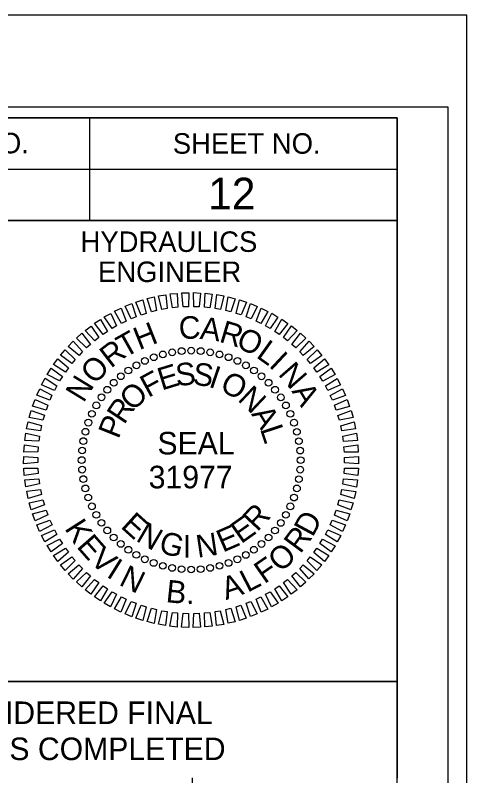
# Model space of a CAD drawing. Extents: x 557032 to 558840, y 515971 to 517218.
# Drawn here: x 558606.3 to 558716.5, y 517032.6 to 517218.2 of the extents above; entities that cross this region are included whole.
import ezdxf

# ---------------------------------------------------------------- set-up
doc = ezdxf.new("R2010")
doc.units = 0
for name, color, linetype in [('Default', 7, 'Continuous'), ('Sheet Cutting Line CELL', 7, 'Continuous'), ('Sheet Data Field CELL', 7, 'Continuous'), ('Sheet Plot Border Inside CELL', 7, 'Continuous'), ('Sheet Plot Border Outside CELL', 7, 'Continuous'), ('Sheet Profile CELL', 7, 'Continuous'), ('Sheet Profile Grid Major CELL', 7, 'Continuous'), ('Sheet Sticker Exception Certification CELL', 7, 'Continuous')]:
    doc.layers.add(name, color=color, linetype=linetype)

msp = doc.modelspace()

# ---------------------------------------------------------------- linework, layer by layer
at = {"layer": 'Default'}
for points in [[(558639.58, 517145.8), (558638.5, 517149.06), (558640.23, 517149.46), (558640.8, 517146.11)], [(558642.12, 517146.38), (558641.27, 517149.71), (558643.03, 517149.99), (558643.36, 517146.61)], [(558644.7, 517146.79), (558644.09, 517150.17), (558645.86, 517150.32), (558645.95, 517146.93)], [(558647.31, 517147.01), (558646.93, 517150.43), (558648.71, 517150.46), (558648.56, 517147.07)], [(558649.92, 517147.06), (558649.78, 517150.49), (558651.55, 517150.4), (558651.18, 517147.02)], [(558652.53, 517146.92), (558652.63, 517150.35), (558654.39, 517150.13), (558653.78, 517146.79)], [(558655.12, 517146.6), (558655.46, 517150.02), (558657.2, 517149.68), (558656.36, 517146.39)], [(558657.68, 517146.1), (558658.26, 517149.48), (558659.98, 517149.02), (558658.9, 517145.8)], [(558634.64, 517144.1), (558633.12, 517147.18), (558634.78, 517147.82), (558635.8, 517144.58)], [(558637.08, 517145.03), (558635.78, 517148.21), (558637.48, 517148.73), (558638.27, 517145.43)], [(558660.2, 517145.42), (558661.02, 517148.76), (558662.7, 517148.18), (558661.4, 517145.04)], [(558662.67, 517144.57), (558663.72, 517147.84), (558665.35, 517147.14), (558663.84, 517144.1)], [(558629.99, 517141.74), (558628.05, 517144.57), (558629.61, 517145.43), (558631.07, 517142.37)], [(558632.27, 517143), (558630.54, 517145.96), (558632.15, 517146.72), (558633.4, 517143.56)], [(558665.08, 517143.54), (558666.34, 517146.74), (558667.93, 517145.93), (558666.21, 517143)], [(558667.4, 517142.36), (558668.89, 517145.45), (558670.41, 517144.53), (558668.5, 517141.73)], [(558627.8, 517140.31), (558625.67, 517143.01), (558627.16, 517143.98), (558628.83, 517141.02)], [(558669.64, 517141.01), (558671.34, 517143.99), (558672.8, 517142.97), (558670.69, 517140.31)], [(558625.71, 517138.74), (558623.4, 517141.28), (558624.82, 517142.35), (558626.7, 517139.52)], [(558671.78, 517139.51), (558673.68, 517142.37), (558675.06, 517141.25), (558672.77, 517138.74)], [(558623.74, 517137.03), (558621.25, 517139.4), (558622.59, 517140.57), (558624.67, 517137.88)], [(558673.81, 517137.86), (558675.91, 517140.58), (558677.21, 517139.37), (558674.75, 517137.03)], [(558621.89, 517135.19), (558619.24, 517137.38), (558620.5, 517138.64), (558622.76, 517136.1)], [(558675.72, 517136.08), (558678, 517138.65), (558679.21, 517137.34), (558676.59, 517135.18)], [(558620.17, 517133.22), (558617.38, 517135.22), (558618.55, 517136.56), (558620.98, 517134.19)], [(558677.5, 517134.17), (558679.95, 517136.57), (558681.07, 517135.19), (558678.31, 517133.21)], [(558618.6, 517131.13), (558615.67, 517132.94), (558616.75, 517134.36), (558619.33, 517132.16)], [(558679.14, 517132.14), (558681.76, 517134.36), (558682.78, 517132.9), (558679.88, 517131.12)], [(558617.17, 517128.94), (558614.13, 517130.54), (558615.1, 517132.03), (558617.83, 517130.01)], [(558680.63, 517130), (558683.4, 517132.03), (558684.32, 517130.51), (558681.31, 517128.93)], [(558615.91, 517126.66), (558612.76, 517128.04), (558613.62, 517129.6), (558616.49, 517127.77)], [(558681.98, 517127.76), (558684.88, 517129.59), (558685.69, 517128.01), (558682.57, 517126.65)], [(558614.8, 517124.29), (558611.57, 517125.45), (558612.32, 517127.06), (558615.3, 517125.45)], [(558683.16, 517125.43), (558686.18, 517127.06), (558686.88, 517125.42), (558683.68, 517124.28)], [(558613.86, 517121.86), (558610.55, 517122.78), (558611.19, 517124.45), (558614.29, 517123.04)], [(558684.18, 517123.02), (558687.31, 517124.44), (558687.89, 517122.76), (558684.62, 517121.84)], [(558613.1, 517119.36), (558609.73, 517120.05), (558610.25, 517121.76), (558613.44, 517120.57)], [(558685.03, 517120.55), (558688.25, 517121.75), (558688.71, 517120.03), (558685.38, 517119.35)], [(558612.51, 517116.82), (558609.1, 517117.27), (558609.5, 517119.01), (558612.76, 517118.05)], [(558685.7, 517118.03), (558689, 517119), (558689.34, 517117.25), (558685.97, 517116.8)], [(558612.1, 517114.24), (558608.67, 517114.46), (558608.95, 517116.21), (558612.26, 517115.48)], [(558686.2, 517115.46), (558689.55, 517116.2), (558689.77, 517114.43), (558686.38, 517114.22)], [(558611.87, 517111.63), (558608.43, 517111.61), (558608.59, 517113.39), (558611.95, 517112.89)], [(558686.51, 517112.87), (558689.91, 517113.37), (558690, 517111.59), (558686.61, 517111.62)], [(558611.82, 517109.02), (558608.39, 517108.76), (558608.42, 517110.54), (558611.81, 517110.28)], [(558686.65, 517110.26), (558690.07, 517110.52), (558690.04, 517108.74), (558686.65, 517109.01)], [(558611.95, 517106.41), (558608.55, 517105.92), (558608.46, 517107.69), (558611.86, 517107.67)], [(558686.6, 517107.65), (558690.03, 517107.67), (558689.88, 517105.9), (558686.52, 517106.4)], [(558612.27, 517103.82), (558608.91, 517103.09), (558608.7, 517104.85), (558612.09, 517105.07)], [(558686.37, 517105.05), (558689.8, 517104.83), (558689.52, 517103.07), (558686.2, 517103.8)], [(558612.76, 517101.26), (558609.47, 517100.29), (558609.13, 517102.04), (558612.5, 517102.49)], [(558685.96, 517102.47), (558689.36, 517102.01), (558688.96, 517100.28), (558685.7, 517101.24)], [(558613.44, 517098.73), (558610.22, 517097.54), (558609.76, 517099.26), (558613.08, 517099.94)], [(558685.37, 517099.93), (558688.73, 517099.23), (558688.21, 517097.53), (558685.03, 517098.72)], [(558614.29, 517096.26), (558611.16, 517094.85), (558610.58, 517096.53), (558613.85, 517097.44)], [(558684.6, 517097.43), (558687.91, 517096.5), (558687.27, 517094.84), (558684.18, 517096.25)], [(558615.31, 517093.86), (558612.28, 517092.23), (558611.59, 517093.87), (558614.79, 517095)], [(558683.66, 517094.99), (558686.9, 517093.84), (558686.15, 517092.22), (558683.16, 517093.84)], [(558616.49, 517091.53), (558613.59, 517089.69), (558612.78, 517091.28), (558615.89, 517092.64)], [(558682.56, 517092.63), (558685.71, 517091.25), (558684.84, 517089.69), (558681.98, 517091.51)], [(558617.83, 517089.29), (558615.06, 517087.25), (558614.15, 517088.78), (558617.16, 517090.35)], [(558681.29, 517090.34), (558684.33, 517088.75), (558683.36, 517087.26), (558680.63, 517089.27)], [(558619.33, 517087.15), (558616.71, 517084.93), (558615.69, 517086.38), (558618.58, 517088.16)], [(558679.87, 517088.15), (558682.79, 517086.35), (558681.72, 517084.93), (558679.13, 517087.13)], [(558620.97, 517085.12), (558618.51, 517082.72), (558617.39, 517084.1), (558620.16, 517086.08)], [(558678.29, 517086.07), (558681.08, 517084.07), (558679.92, 517082.72), (558677.49, 517085.1)], [(558622.75, 517083.21), (558620.47, 517080.64), (558619.25, 517081.94), (558621.87, 517084.11)], [(558676.58, 517084.1), (558679.22, 517081.91), (558677.96, 517080.65), (558675.71, 517083.19)], [(558624.66, 517081.42), (558622.56, 517078.7), (558621.26, 517079.92), (558623.72, 517082.26)], [(558626.69, 517079.78), (558624.78, 517076.92), (558623.4, 517078.04), (558625.69, 517080.55)], [(558672.76, 517080.54), (558675.07, 517078), (558673.65, 517076.93), (558671.77, 517079.76)], [(558674.73, 517082.25), (558677.21, 517079.88), (558675.87, 517078.72), (558673.8, 517081.41)], [(558628.83, 517078.28), (558627.13, 517075.29), (558625.67, 517076.31), (558627.78, 517078.98)], [(558670.67, 517078.97), (558672.8, 517076.28), (558671.31, 517075.31), (558669.63, 517078.26)], [(558631.06, 517076.93), (558629.58, 517073.83), (558628.05, 517074.75), (558629.97, 517077.55)], [(558668.48, 517077.55), (558670.42, 517074.72), (558668.86, 517073.85), (558667.39, 517076.92)], [(558633.39, 517075.74), (558632.12, 517072.55), (558630.54, 517073.36), (558632.26, 517076.29)], [(558635.79, 517074.72), (558634.75, 517071.45), (558633.11, 517072.14), (558634.62, 517075.18)], [(558663.82, 517075.19), (558665.35, 517072.11), (558663.69, 517071.47), (558662.66, 517074.71)], [(558666.19, 517076.29), (558667.93, 517073.32), (558666.31, 517072.57), (558665.06, 517075.73)], [(558638.26, 517073.87), (558637.45, 517070.53), (558635.77, 517071.11), (558637.06, 517074.25)], [(558640.78, 517073.19), (558640.21, 517069.8), (558638.49, 517070.27), (558639.56, 517073.49)], [(558658.89, 517073.49), (558659.97, 517070.23), (558658.23, 517069.83), (558657.67, 517073.18)], [(558661.38, 517074.25), (558662.69, 517071.07), (558660.99, 517070.56), (558660.19, 517073.86)], [(558643.35, 517072.69), (558643.01, 517069.27), (558641.26, 517069.61), (558642.11, 517072.9)], [(558645.94, 517072.37), (558645.84, 517068.93), (558644.07, 517069.15), (558644.69, 517072.49)], [(558648.55, 517072.23), (558648.69, 517068.8), (558646.91, 517068.89), (558647.29, 517072.27)], [(558651.16, 517072.27), (558651.54, 517068.86), (558649.76, 517068.83), (558649.9, 517072.22)], [(558653.76, 517072.5), (558654.38, 517069.12), (558652.6, 517068.97), (558652.51, 517072.36)], [(558656.34, 517072.91), (558657.19, 517069.58), (558655.43, 517069.3), (558655.1, 517072.68)]]:
    msp.add_lwpolyline(points, close=True, dxfattribs=at)
for centre in [(558642.33, 517135.43), (558644.6, 517135.93), (558646.91, 517136.24), (558649.24, 517136.34), (558651.56, 517136.24), (558653.87, 517135.93), (558656.15, 517135.43), (558637.96, 517133.84), (558640.11, 517134.73), (558658.37, 517134.73), (558660.52, 517133.84), (558635.89, 517132.77), (558662.59, 517132.76), (558632.08, 517130.1), (558633.92, 517131.51), (558664.55, 517131.51), (558666.4, 517130.09), (558630.36, 517128.52), (558668.11, 517128.52), (558628.79, 517126.81), (558669.69, 517126.8), (558627.37, 517124.96), (558671.1, 517124.95), (558626.12, 517123), (558672.35, 517122.99), (558625.04, 517120.93), (558673.43, 517120.92), (558624.15, 517118.78), (558674.32, 517118.77), (558623.45, 517116.56), (558675.02, 517116.55), (558622.94, 517114.28), (558675.52, 517114.27), (558622.64, 517111.98), (558675.83, 517111.97), (558622.54, 517109.65), (558675.93, 517109.64), (558622.64, 517107.32), (558675.83, 517107.31), (558622.94, 517105.01), (558675.52, 517105), (558623.44, 517102.74), (558675.02, 517102.73), (558624.14, 517100.52), (558674.32, 517100.51), (558625.04, 517098.37), (558673.43, 517098.36), (558626.11, 517096.3), (558672.35, 517096.29), (558627.36, 517094.34), (558671.1, 517094.33), (558628.78, 517092.49), (558630.35, 517090.77), (558668.11, 517090.76), (558669.68, 517092.48), (558632.07, 517089.2), (558666.39, 517089.19), (558633.92, 517087.78), (558664.54, 517087.77), (558635.88, 517086.53), (558637.95, 517085.45), (558660.51, 517085.45), (558662.58, 517086.52), (558640.1, 517084.56), (558642.32, 517083.86), (558644.59, 517083.35), (558653.86, 517083.35), (558656.14, 517083.86), (558658.36, 517084.56), (558646.9, 517083.05), (558649.23, 517082.95), (558651.55, 517083.05)]:
    msp.add_circle(centre, 0.826, dxfattribs=at)
at = {"layer": 'Sheet Cutting Line CELL'}
msp.add_line((558716.45, 517218.17), (557032.45, 517218.17), dxfattribs=at)
at = {"layer": 'Sheet Plot Border Inside CELL'}
msp.add_lwpolyline([(557045.45, 516140.62), (558711.95, 516140.62), (558711.95, 517195.72), (557045.45, 517195.72)], close=True, dxfattribs=at)
at = {"layer": 'Sheet Plot Border Outside CELL'}
msp.add_lwpolyline([(557032.45, 516118.17), (558716.45, 516118.17), (558716.45, 517218.17), (557032.45, 517218.17)], close=True, dxfattribs=at)
at = {"layer": 'Sheet Profile CELL'}
for p, q in [((558624.45, 517193.12), (558624.45, 517168.12)), ((558499.4, 517180.62), (558699.45, 517180.62))]:
    msp.add_line(p, q, dxfattribs=at)
for points in [[(558699.45, 517193.17), (557199.45, 517193.17), (557199.45, 516143.17), (558699.45, 516143.17)], [(558499.4, 517193.17), (558699.45, 517193.17), (558699.45, 517168.12), (558499.4, 517168.12)], [(558599.45, 517168.12), (558699.45, 517168.12), (558699.45, 517055.62), (558599.45, 517055.62)]]:
    msp.add_lwpolyline(points, close=True, dxfattribs=at)
at = {"layer": 'Sheet Profile Grid Major CELL'}
msp.add_lwpolyline([(558649.45, 517032.12), (558649.45, 516693.17), (558699.45, 516693.17), (558699.45, 517043.17)], dxfattribs=at)
at = {"layer": 'Sheet Sticker Exception Certification CELL'}
for p, q in [((558499.4, 517055.62), (558699.44, 517055.62)), ((558499.4, 517055.62), (558699.44, 517055.62)), ((558699.44, 517055.6), (558699.44, 517032.1)), ((558699.44, 517055.6), (558699.44, 517032.1))]:
    msp.add_line(p, q, dxfattribs=at)

# ---------------------------------------------------------------- texts
at = {"layer": 'Default'}
for s, height, rotation, p in [('C', 5.5, 1.9509, (558646.3, 517139.15)), ('A', 5.5, 352.4458, (558651.21, 517139.23)), ('R', 5.5, 343.3983, (558655.84, 517138.55)), ('H', 5.5, 21.5901, (558636.55, 517136.44)), ('O', 5.5, 335.1897, (558659.9, 517137.31)), ('T', 5.5, 29.3793, (558633.04, 517134.48)), ('R', 5.5, 37.5879, (558629.66, 517131.91)), ('L', 5.5, 324.4645, (558664.86, 517134.84)), ('I', 5.5, 316.9994, (558668, 517132.59)), ('O', 5.5, 48.3131, (558625.86, 517127.88)), ('E', 5.5, 16.975, (558642.05, 517126.59)), ('S', 5.5, 5.2127, (558645.65, 517127.69)), ('S', 5.5, 353.2538, (558649.47, 517128.05)), ('I', 5.5, 341.2948, (558653.28, 517127.6)), ('N', 5.5, 311.0594, (558670.28, 517130.53)), ('F', 5.5, 28.6529, (558638.77, 517124.78)), ('O', 5.5, 332.5394, (558655.96, 517126.77)), ('N', 5.5, 58.5235, (558622.99, 517123.45)), ('O', 5.5, 44.4617, (558635.04, 517121.36)), ('N', 5.5, 316.7306, (558660.37, 517124.29)), ('A', 5.5, 300.849, (558673.65, 517126.47)), ('R', 5.5, 56.5612, (558632.9, 517118.12)), ('A', 5.5, 301.6806, (558663.8, 517120.89)), ('P', 5.5, 68.3234, (558631.51, 517114.61)), ('L', 5.5, 288.3447, (558666, 517117.23)), ('SEAL', 5.504, 359.989, (558641.01, 517111.02)), ('31977', 5.504, 359.989, (558638.88, 517102.76)), ('R', 5.5, 47.032, (558665.34, 517092.01)), ('K', 5.5, 302.6028, (558618.24, 517092.98)), ('E', 5.5, 317.8396, (558631.83, 517093.29)), ('E', 5.5, 35.2697, (558661.41, 517089.09)), ('D', 5.5, 61.6895, (558678.86, 517090.66)), ('N', 5.5, 329.6019, (558635.52, 517090.08)), ('E', 5.5, 23.5075, (558656.96, 517087.04)), ('E', 5.5, 311.3071, (558621.11, 517088.48)), ('G', 5.5, 344.6519, (558641.07, 517087.2)), ('N', 5.5, 8.4574, (558650.83, 517085.81)), ('R', 5.5, 53.4809, (558675.85, 517086.62)), ('I', 5.5, 359.702, (558647.18, 517085.85)), ('V', 5.5, 319.287, (558624.32, 517084.78)), ('O', 5.5, 42.7557, (558671.1, 517082.07)), ('F', 5.5, 34.833, (558667.09, 517079.32)), ('I', 5.5, 327.9723, (558628.36, 517081.31)), ('N', 5.5, 333.9122, (558631.41, 517079.3)), ('L', 5.5, 27.3679, (558663, 517077.26)), ('A', 5.5, 18.3204, (558657.73, 517075.49)), ('B', 5.5, 354.009, (558642.92, 517075.02)), ('.', 5.5, 2.3511, (558648.01, 517074.47))]:
    msp.add_text(s, height=height, rotation=rotation, dxfattribs=at).set_placement(p)
at = {"layer": 'Sheet Data Field CELL'}
msp.add_text('12 ', height=7.75, dxfattribs=at).set_placement((558653.39, 517170.78))
at = {"layer": 'Sheet Profile CELL'}
for s, height, p in [('PROJECT REFERENCE NO.', 5.0001, (558521.62, 517184.48)), ('SHEET NO.', 5, (558644.77, 517184.38)), ('HYDRAULICS', 5, (558622.27, 517160.43)), ('ENGINEER', 5, (558626.52, 517153.08))]:
    msp.add_text(s, height=height, dxfattribs=at).set_placement(p)
at = {"layer": 'Sheet Sticker Exception Certification CELL'}
for s, p in [('DOCUMENT NOT CONSIDERED FINAL', (558520.47, 517045.27)), ('DOCUMENT NOT CONSIDERED FINAL', (558520.47, 517045.27)), ('UNLESS ALL SIGNATURES COMPLETED', (558515.4, 517036.47)), ('UNLESS ALL SIGNATURES COMPLETED', (558515.4, 517036.47))]:
    msp.add_text(s, height=5.5, dxfattribs=at).set_placement(p)

doc.saveas('drawing.dxf')
